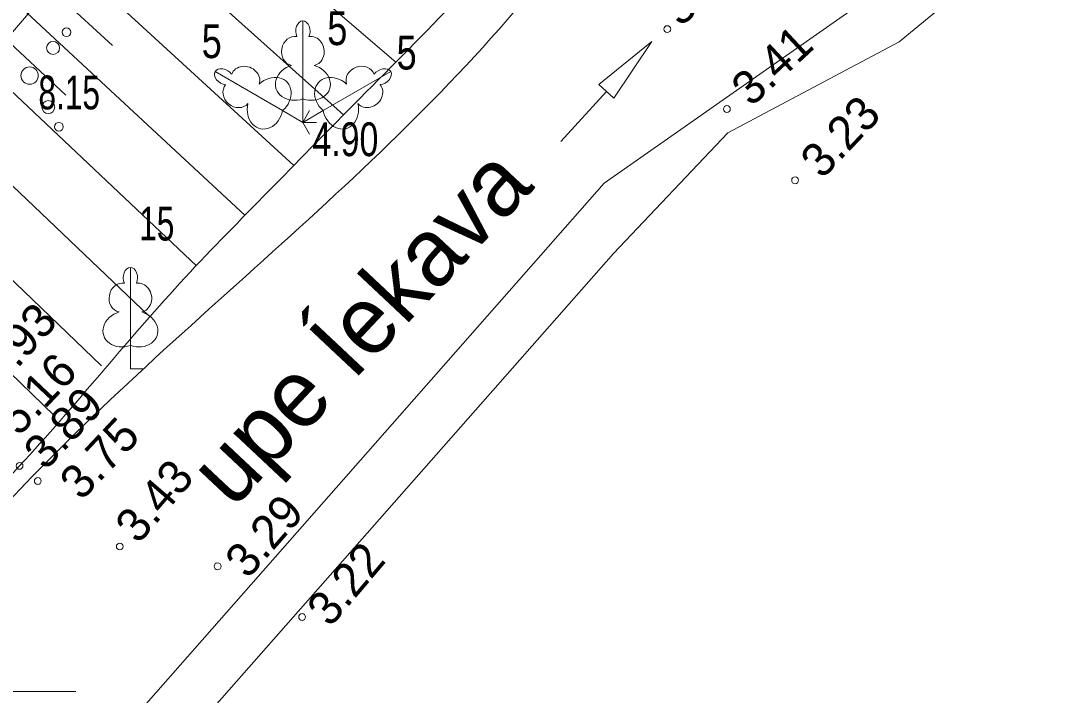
# Model space of a CAD drawing. Extents: x -1325 to -1182, y 698 to 905.
# Drawn here: x -1247.78 to -1232.55, y 804.12 to 814.1 of the extents above; entities that cross this region are included whole.
import ezdxf

# ---------------------------------------------------------------- set-up
doc = ezdxf.new("R2010")
doc.units = 0
doc.header["$LTSCALE"] = 0.2
for name, color, linetype, lineweight in [('1', 7, 'Continuous', 13), ('19', 7, 'Continuous', 13), ('20', 7, 'Continuous', 13), ('21', 7, 'Continuous', 13), ('4', 7, 'Continuous', 13), ('5', 7, 'Continuous', 13), ('55', 7, 'Continuous', 13), ('6', 7, 'Continuous', 13), ('62', 7, 'Continuous', 13)]:
    doc.layers.add(name, color=color, linetype=linetype, lineweight=lineweight)
for name, color, linetype in [('12', 7, 'Continuous'), ('27', 7, 'Continuous'), ('8', 7, 'Continuous')]:
    doc.layers.add(name, color=color, linetype=linetype)

msp = doc.modelspace()

# ---------------------------------------------------------------- linework, layer by layer
at = {"layer": '1'}
for p, q in [((-1245.744, 816.505), (-1242.223, 813.478)), ((-1246.402, 815.752), (-1242.999, 812.703)), ((-1247.073, 815.011), (-1243.736, 811.955)), ((-1247.411, 814.643), (-1246.417, 813.726)), ((-1247.751, 814.276), (-1244.454, 811.216)), ((-1248.092, 813.91), (-1247.107, 812.991)), ((-1248.434, 813.545), (-1245.172, 810.47)), ((-1249.121, 812.819), (-1245.88, 809.729)), ((-1249.813, 812.097), (-1246.578, 808.992)), ((-1250.506, 811.376), (-1247.272, 808.252))]:
    msp.add_line(p, q, dxfattribs=at)
msp.add_spline([(-1235.8, 825.801), (-1237.913, 825.174), (-1239.202, 823.346), (-1241.709, 821.268), (-1246.557, 815.58), (-1256.525, 805.053), (-1260.591, 799.146), (-1261.416, 795.29), (-1262.741, 791.444), (-1262.206, 785.139)], degree=3, dxfattribs=at)
at = {"layer": '19'}
msp.add_spline([(-1253.457, 785.393), (-1253.726, 794.104), (-1251.637, 801.373), (-1250.122, 804.26), (-1247.608, 807.348), (-1239.437, 815.544), (-1236.507, 819.221), (-1228.799, 821.851), (-1223.357, 826.161), (-1220.079, 827.95)], degree=3, dxfattribs=at)
at = {"layer": '20'}
msp.add_lwpolyline([(-1251.428, 785.238), (-1264.287, 784.95), (-1270.386, 788.761), (-1278.142, 789.522), (-1278.429, 820.375), (-1260.691, 834.371), (-1258.18, 840.695), (-1250.014, 845.483), (-1229.719, 840.991), (-1227.82, 835.408), (-1218.991, 825.806), (-1239.144, 811.691), (-1246.245, 803.625), (-1250.023, 795.415), (-1251.371, 785.664)], close=True, dxfattribs=at)
at = {"layer": '21'}
msp.add_line((-1246.96, 804.174), (-1249.264, 804.174), dxfattribs=at)
at = {"layer": '4'}
msp.add_line((-1239.786, 812.309), (-1239.112, 813.048), dxfattribs=at)
for points in [[(-1238.439, 813.787), (-1239.001, 812.947), (-1239.223, 813.149)], [(-1239.112, 813.048), (-1239.001, 812.947), (-1238.439, 813.787), (-1239.223, 813.149)]]:
    msp.add_lwpolyline(points, close=True, dxfattribs=at)
at = {"layer": '5'}
for p, q in [((-1243.601, 814.091), (-1243.601, 812.938)), ((-1243.511, 813.859), (-1243.512, 813.859)), ((-1244.9, 813.341), (-1243.901, 812.764)), ((-1244.654, 813.302), (-1244.655, 813.302)), ((-1242.302, 813.341), (-1243.3, 812.764)), ((-1242.458, 813.147), (-1242.458, 813.149)), ((-1243.601, 812.938), (-1243.601, 812.591)), ((-1243.901, 812.764), (-1243.601, 812.591)), ((-1243.601, 812.591), (-1243.501, 812.764)), ((-1243.3, 812.764), (-1243.601, 812.591)), ((-1243.601, 812.591), (-1243.401, 812.591)), ((-1243.601, 812.591), (-1243.501, 812.418)), ((-1246.152, 810.444), (-1246.152, 809.291)), ((-1246.062, 810.212), (-1246.063, 810.212)), ((-1246.152, 809.291), (-1246.152, 808.944)), ((-1246.152, 808.944), (-1245.952, 808.944))]:
    msp.add_line(p, q, dxfattribs=at)
for centre, radius in [((-1247.0976, 813.9223), 0.064), ((-1247.2941, 813.6906), 0.096), ((-1247.6416, 813.283), 0.128), ((-1247.3651, 812.8161), 0.096), ((-1247.2077, 812.5268), 0.064)]:
    msp.add_circle(centre, radius, dxfattribs=at)
for centre, major_axis, ratio, start_param, end_param in [((-1243.6002, 813.941), (0, -0.1499), 0.707107, 3.1453698, 5.2874846), ((-1243.601, 813.941), (0, -0.1499), 0.707107, 0.9957007, 3.1378155), ((-1243.7289, 813.6462), (-0.0387, -0.2124), 0.861323, 3.1415927, 6.2831853), ((-1243.4723, 813.6462), (0.0387, -0.2124), 0.861323, 6.2831853, 9.424778), ((-1244.77, 813.2656), (0.1298, -0.075), 0.707107, 0.9957007, 3.1378155), ((-1244.4503, 813.2297), (0.2033, -0.0727), 0.861323, 6.2831853, 9.424778), ((-1243.6902, 813.1839), (0.3068, 0.0951), 0.814445, 1.5707963, 4.7520146), ((-1243.511, 813.1839), (-0.3068, 0.0951), 0.814445, 1.5311707, 4.712389), ((-1242.7509, 813.2297), (-0.2033, -0.0727), 0.861323, 3.1415927, 6.2831853), ((-1242.4312, 813.2656), (-0.1298, -0.075), 0.707107, 3.1453698, 5.2874846), ((-1244.7696, 813.2663), (0.1298, -0.075), 0.707107, 3.1453698, 5.2874846), ((-1244.0693, 812.965), (-0.2358, -0.2182), 0.814445, 1.5311707, 4.712389), ((-1243.1319, 812.965), (0.2358, -0.2182), 0.814445, 1.5707963, 4.7520146), ((-1242.4316, 813.2663), (-0.1298, -0.075), 0.707107, 0.9957007, 3.1378155), ((-1244.5786, 813.0075), (0.1646, -0.1397), 0.861323, 3.1415927, 6.2831853), ((-1242.6226, 813.0075), (-0.1646, -0.1397), 0.861323, 6.2831853, 9.424778), ((-1244.1588, 812.8099), (0.071, 0.3133), 0.814445, 1.5707963, 4.7520146), ((-1243.0423, 812.8099), (-0.071, 0.3133), 0.814445, 1.5311707, 4.712389), ((-1246.1512, 810.294), (0, -0.1499), 0.707107, 3.1453698, 5.2874846), ((-1246.152, 810.294), (0, -0.1499), 0.707107, 0.9957007, 3.1378155), ((-1246.2799, 809.9992), (-0.0387, -0.2124), 0.861323, 3.1415927, 6.2831853), ((-1246.0233, 809.9992), (0.0387, -0.2124), 0.861323, 6.2831853, 9.424778), ((-1246.2412, 809.5369), (0.3068, 0.0951), 0.814445, 1.5707963, 4.7520146), ((-1246.062, 809.5369), (-0.3068, 0.0951), 0.814445, 1.5311707, 4.712389)]:
    msp.add_ellipse(centre, major_axis=major_axis, ratio=ratio, start_param=start_param, end_param=end_param, dxfattribs=at)
at = {"layer": '55'}
msp.add_lwpolyline([(-1251.177, 781.942), (-1250.876, 788.586), (-1249.424, 796.058), (-1246.365, 802.296), (-1239.008, 810.653), (-1237.317, 812.435), (-1234.783, 813.781), (-1227.269, 819.96), (-1220.231, 823.644), (-1218.172, 824.289), (-1214.858, 828.794), (-1213.693, 830.709)], dxfattribs=at)
at = {"layer": '6'}
for centre in [(-1238.2116, 813.97), (-1237.3306, 812.788), (-1236.3226, 811.734), (-1247.7906, 807.511), (-1247.5216, 807.288), (-1246.3086, 806.319), (-1244.8616, 806.026), (-1243.6126, 805.277)]:
    msp.add_circle(centre, 0.05, dxfattribs=at)
at = {"layer": '62'}
msp.add_spline([(-1254.434, 786.21), (-1255.853, 794.247), (-1253.372, 799.782), (-1252.196, 801.907), (-1252.102, 801.965), (-1250.675, 804.058), (-1247.791, 807.511), (-1245.419, 810.213), (-1244.186, 811.494), (-1242.939, 812.763), (-1240.149, 815.75), (-1236.129, 820.169), (-1233.075, 822.242), (-1235.394, 825.816)], degree=3, dxfattribs=at)

# ---------------------------------------------------------------- texts
at = {"layer": '12'}
for s, width, p in [(' 5', 0.8, (-1243.389, 813.733)), (' 5', 0.8, (-1245.246, 813.541)), (' 5', 0.8, (-1242.364, 813.372)), (' 15', 0.7, (-1246.152, 810.844))]:
    msp.add_text(s, height=0.5, dxfattribs=dict(at, width=width)).set_placement(p)
at = {"layer": '27'}
msp.add_text('upe Íekava', height=1, rotation=46.796, dxfattribs=at).set_placement((-1244.64, 806.86))
at = {"layer": '8'}
for s, rotation, p in [(' 3.40', 40.947, (-1238.16, 813.869)), (' 3.41', 43.053, (-1237.105, 812.681)), (' 3.23', 46.533, (-1236.049, 811.604)), (' 5.93', 48.163, (-1248.196, 808.525)), (' 5.16', 46.615, (-1247.93, 807.8)), (' 3.89', 46.961, (-1247.532, 807.294)), (' 3.75', 46.703, (-1247.002, 806.848)), (' 3.43', 49.314, (-1246.156, 806.2)), (' 3.29', 48.826, (-1244.537, 805.685)), (' 3.22', 49.772, (-1243.317, 804.969))]:
    msp.add_text(s, height=0.5, rotation=rotation, dxfattribs=at).set_placement(p)
for s, width, p in [(' 8.15', 0.7, (-1247.642, 812.783)), (' 4.90', 0.75, (-1243.6, 812.091))]:
    msp.add_text(s, height=0.5, dxfattribs=dict(at, width=width)).set_placement(p)

doc.saveas('drawing.dxf')
